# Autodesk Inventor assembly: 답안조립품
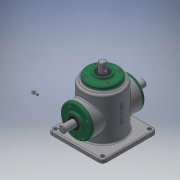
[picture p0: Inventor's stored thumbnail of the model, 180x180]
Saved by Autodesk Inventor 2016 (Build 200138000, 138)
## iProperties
Created: 2019-08
Part Number: 답안조립품
Material: 일반
Document SubType Name: Assembly
Designer: user
Author: user
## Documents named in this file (16)
- D:\490823V1004\답안조립품.iam
- D:\490823V1004\메인 베벨기어.ipt
- D:\490823V1004\메인 축.ipt
- 메인 축.ipt
- D:\490823V1004\베어링 6203.ipt
- D:\490823V1004\본체.ipt
- D:\490823V1004\볼트 M4.ipt
- 볼트 M4.ipt
- D:\490823V1004\서브 베벨기어.ipt
- D:\490823V1004\서브 축.ipt
- 서브 축.ipt
- D:\490823V1004\오일 실.ipt
- 오일 실.ipt
- D:\490823V1004\커버.ipt
- D:\490823V1004\키 4x4.ipt
- D:\490823V1004\키 5x5.ipt
